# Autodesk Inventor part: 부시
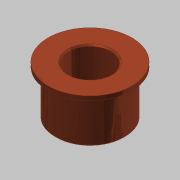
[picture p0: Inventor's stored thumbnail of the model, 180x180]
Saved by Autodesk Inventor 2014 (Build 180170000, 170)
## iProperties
Created: 2015-10
Part Number: 부시
Document SubType Name: Modeling
Designer: mdu
Density: 7.86 g/cm^3
Material: 강철, 연강
Mass: 364.706 g
Surface Area: 129.307 cm^2
Volume: 46.4003 cm^3
Appearance: 구리 - 새틴
Author: mdu
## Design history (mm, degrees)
sketch "스케치1"
  geometry: C1 r 31 at (0, 0) reference; C2 r 25 at (0, 0) reference; C3 r 30 at (0, 0) reference; 1 further point
  node "참조1"
  node "참조2"
  node "참조4"
extrude "돌출1" new body sketch "스케치1" distance "d0" = 3; taper "d1" = 0 deg
extrude "돌출2" join sketch "스케치1" distance "d2" = 35; taper "d3" = 0 deg
chamfer "모따기1" distance "d6" = 1; stored, may be unused: second distance "d7" = 2, angle "d8" = 45 deg
sketch "스케치3"
  geometry: C1 r 15 at (0, 0); 1 further point
  constraints: 1 centre point, 1 coincident
  dimensions: "d13" = 30 diameter of C1
extrude "돌출4" cut sketch "스케치3" stored distance "d14" = 10; taper "d15" = 0 deg
chamfer "모따기3" distance "d16" = 1; stored, may be unused: second distance "d17" = 2, angle "d18" = 45 deg
node "솔리드1"
